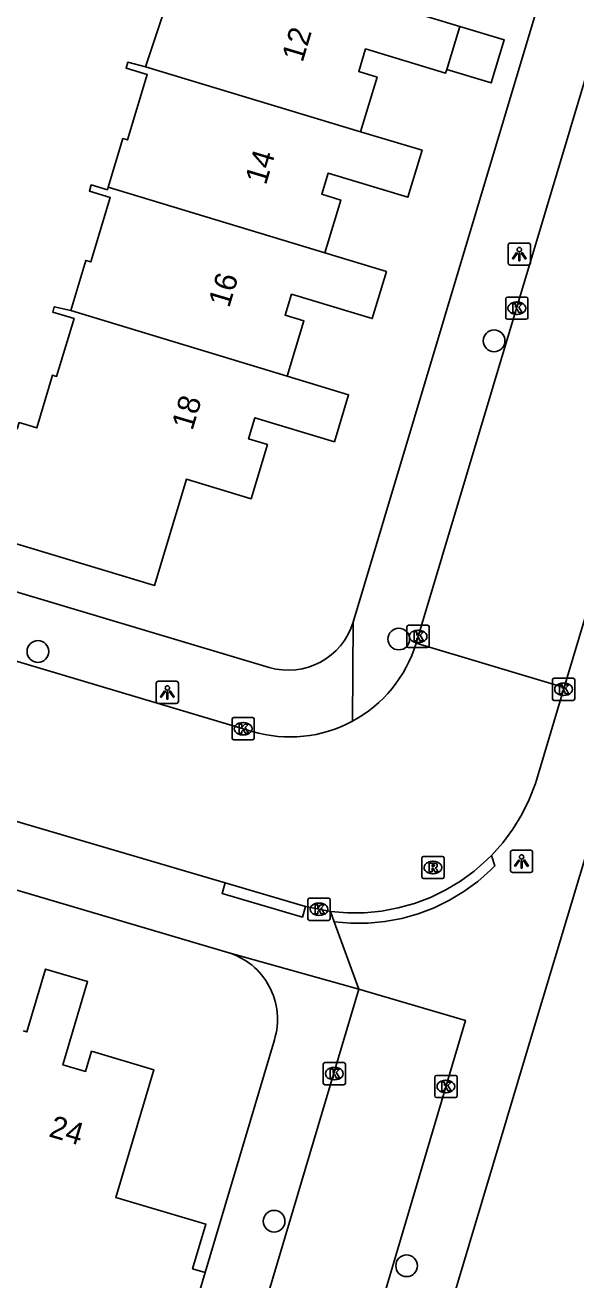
# Model space of a CAD drawing. Extents: x 162186 to 163152, y 385513 to 386513.
# Drawn here: x 162667.2 to 162692, y 386082.7 to 386139.3 of the extents above; entities that cross this region are included whole.
import ezdxf

# ---------------------------------------------------------------- set-up
doc = ezdxf.new("R2010")
doc.units = 0
for name, color, linetype in [('IMGEO_Boom', 7, 'Continuous'), ('IMGEO_Kolk', 7, 'Continuous'), ('IMGEO_Lichtpunt', 7, 'Continuous'), ('IMGEO_Pand', 7, 'Continuous'), ('IMGEO_Pand_nummerreeks', 7, 'Continuous'), ('IMGEO_Rijbaan_lokaal_open', 7, 'Continuous'), ('IMGEO_Rioolput', 7, 'Continuous'), ('IMGEO_Voetpad_open', 7, 'Continuous')]:
    doc.layers.add(name, color=color, linetype=linetype)

msp = doc.modelspace()

# ---------------------------------------------------------------- linework, layer by layer
at = {"layer": 'IMGEO_Boom'}
for centre in [(162688.354, 386125.044), (162684.062, 386111.611), (162667.801, 386111.048), (162678.444, 386085.382), (162684.416, 386083.376)]:
    msp.add_circle(centre, 0.489, dxfattribs=at)
at = {"layer": 'IMGEO_Kolk'}
for p, q in [((162688.957, 386127.013), (162689.809, 386127.013)), ((162688.882, 386126.087), (162688.882, 386126.939)), ((162689.37, 386126.793), (162689.395, 386126.793)), ((162689.883, 386126.939), (162689.883, 386126.087)), ((162689.809, 386126.013), (162688.957, 386126.013)), ((162689.393, 386126.233), (162689.368, 386126.233)), ((162684.431, 386111.302), (162684.431, 386112.154)), ((162684.506, 386112.228), (162685.358, 386112.228)), ((162684.919, 386112.008), (162684.944, 386112.008)), ((162685.432, 386112.154), (162685.432, 386111.302)), ((162685.358, 386111.228), (162684.506, 386111.228)), ((162684.942, 386111.448), (162684.917, 386111.448)), ((162690.987, 386108.92), (162690.987, 386109.772)), ((162691.062, 386109.846), (162691.914, 386109.846)), ((162691.475, 386109.626), (162691.5, 386109.626)), ((162691.988, 386109.772), (162691.988, 386108.92)), ((162691.498, 386109.066), (162691.473, 386109.066)), ((162691.914, 386108.846), (162691.062, 386108.846)), ((162676.549, 386107.144), (162676.549, 386107.996)), ((162676.624, 386108.07), (162677.476, 386108.07)), ((162677.037, 386107.85), (162677.062, 386107.85)), ((162677.55, 386107.996), (162677.55, 386107.144)), ((162677.06, 386107.29), (162677.035, 386107.29)), ((162677.476, 386107.07), (162676.624, 386107.07)), ((162679.967, 386099.011), (162679.967, 386099.863)), ((162680.042, 386099.937), (162680.894, 386099.937)), ((162680.968, 386099.863), (162680.968, 386099.011)), ((162680.455, 386099.717), (162680.48, 386099.717)), ((162680.894, 386098.937), (162680.042, 386098.937)), ((162680.478, 386099.157), (162680.453, 386099.157)), ((162680.73, 386092.532), (162681.582, 386092.532)), ((162680.655, 386091.606), (162680.655, 386092.458)), ((162681.143, 386092.312), (162681.168, 386092.312)), ((162681.656, 386092.458), (162681.656, 386091.606)), ((162685.759, 386091.954), (162686.611, 386091.954)), ((162681.582, 386091.532), (162680.73, 386091.532)), ((162681.166, 386091.752), (162681.141, 386091.752)), ((162685.684, 386091.028), (162685.684, 386091.88)), ((162686.172, 386091.734), (162686.197, 386091.734)), ((162686.685, 386091.88), (162686.685, 386091.028)), ((162686.611, 386090.954), (162685.759, 386090.954)), ((162686.195, 386091.174), (162686.17, 386091.174))]:
    msp.add_line(p, q, dxfattribs=at)
for points in [[(162688.957, 386127.013), (162689.809, 386127.013)], [(162688.882, 386126.087), (162688.882, 386126.939)], [(162689.203, 386126.713), (162689.326, 386126.713), (162689.326, 386126.562), (162689.456, 386126.713), (162689.62, 386126.713), (162689.474, 386126.562), (162689.627, 386126.313), (162689.475, 386126.313), (162689.39, 386126.477), (162689.326, 386126.41), (162689.326, 386126.313), (162689.203, 386126.313), (162689.203, 386126.713)], [(162689.883, 386126.939), (162689.883, 386126.087)], [(162689.809, 386126.013), (162688.957, 386126.013)], [(162684.431, 386111.302), (162684.431, 386112.154)], [(162684.506, 386112.228), (162685.358, 386112.228)], [(162684.752, 386111.928), (162684.875, 386111.928), (162684.875, 386111.777), (162685.005, 386111.928), (162685.169, 386111.928), (162685.023, 386111.777), (162685.176, 386111.528), (162685.024, 386111.528), (162684.939, 386111.692), (162684.875, 386111.625), (162684.875, 386111.528), (162684.752, 386111.528), (162684.752, 386111.928)], [(162685.432, 386112.154), (162685.432, 386111.302)], [(162685.358, 386111.228), (162684.506, 386111.228)], [(162690.987, 386108.92), (162690.987, 386109.772)], [(162691.062, 386109.846), (162691.914, 386109.846)], [(162691.308, 386109.546), (162691.431, 386109.546), (162691.431, 386109.395), (162691.561, 386109.546), (162691.725, 386109.546), (162691.579, 386109.395), (162691.732, 386109.146), (162691.58, 386109.146), (162691.495, 386109.31), (162691.431, 386109.243), (162691.431, 386109.146), (162691.308, 386109.146), (162691.308, 386109.546)], [(162691.988, 386109.772), (162691.988, 386108.92)], [(162691.914, 386108.846), (162691.062, 386108.846)], [(162676.549, 386107.144), (162676.549, 386107.996)], [(162676.624, 386108.07), (162677.476, 386108.07)], [(162676.87, 386107.77), (162676.993, 386107.77), (162676.993, 386107.619), (162677.123, 386107.77), (162677.287, 386107.77), (162677.141, 386107.619), (162677.294, 386107.37), (162677.142, 386107.37), (162677.057, 386107.534), (162676.993, 386107.467), (162676.993, 386107.37), (162676.87, 386107.37), (162676.87, 386107.77)], [(162677.55, 386107.996), (162677.55, 386107.144)], [(162677.476, 386107.07), (162676.624, 386107.07)], [(162679.967, 386099.011), (162679.967, 386099.863)], [(162680.042, 386099.937), (162680.894, 386099.937)], [(162680.968, 386099.863), (162680.968, 386099.011)], [(162680.288, 386099.637), (162680.411, 386099.637), (162680.411, 386099.486), (162680.541, 386099.637), (162680.705, 386099.637), (162680.559, 386099.486), (162680.712, 386099.237), (162680.56, 386099.237), (162680.475, 386099.401), (162680.411, 386099.334), (162680.411, 386099.237), (162680.288, 386099.237), (162680.288, 386099.637)], [(162680.894, 386098.937), (162680.042, 386098.937)], [(162680.73, 386092.532), (162681.582, 386092.532)], [(162680.655, 386091.606), (162680.655, 386092.458)], [(162680.976, 386092.232), (162681.099, 386092.232), (162681.099, 386092.081), (162681.229, 386092.232), (162681.393, 386092.232), (162681.247, 386092.081), (162681.4, 386091.832), (162681.248, 386091.832), (162681.163, 386091.996), (162681.099, 386091.929), (162681.099, 386091.832), (162680.976, 386091.832), (162680.976, 386092.232)], [(162681.656, 386092.458), (162681.656, 386091.606)], [(162685.759, 386091.954), (162686.611, 386091.954)], [(162681.582, 386091.532), (162680.73, 386091.532)], [(162685.684, 386091.028), (162685.684, 386091.88)], [(162686.005, 386091.654), (162686.128, 386091.654), (162686.128, 386091.503), (162686.258, 386091.654), (162686.422, 386091.654), (162686.276, 386091.503), (162686.429, 386091.254), (162686.277, 386091.254), (162686.192, 386091.418), (162686.128, 386091.351), (162686.128, 386091.254), (162686.005, 386091.254), (162686.005, 386091.654)], [(162686.685, 386091.88), (162686.685, 386091.028)], [(162686.611, 386090.954), (162685.759, 386090.954)]]:
    msp.add_lwpolyline(points, dxfattribs=at)
for centre, start, end in [((162688.959, 386126.937), 91.552, 178.448), ((162688.959, 386126.937), 91.552, 178.448), ((162689.807, 386126.937), 1.552, 88.448), ((162689.807, 386126.937), 1.552, 88.448), ((162688.959, 386126.089), 181.552, 268.448), ((162688.959, 386126.089), 181.552, 268.448), ((162689.807, 386126.089), 271.552, 358.448), ((162689.807, 386126.089), 271.552, 358.448), ((162684.508, 386112.152), 91.552, 178.448), ((162684.508, 386112.152), 91.552, 178.448), ((162685.356, 386112.152), 1.552, 88.448), ((162685.356, 386112.152), 1.552, 88.448), ((162684.508, 386111.304), 181.552, 268.448), ((162684.508, 386111.304), 181.552, 268.448), ((162685.356, 386111.304), 271.552, 358.448), ((162685.356, 386111.304), 271.552, 358.448), ((162691.064, 386109.77), 91.552, 178.448), ((162691.064, 386109.77), 91.552, 178.448), ((162691.912, 386109.77), 1.552, 88.448), ((162691.912, 386109.77), 1.552, 88.448), ((162691.064, 386108.922), 181.552, 268.448), ((162691.064, 386108.922), 181.552, 268.448), ((162691.912, 386108.922), 271.552, 358.448), ((162691.912, 386108.922), 271.552, 358.448), ((162676.626, 386107.994), 91.552, 178.448), ((162676.626, 386107.994), 91.552, 178.448), ((162677.474, 386107.994), 1.552, 88.448), ((162677.474, 386107.994), 1.552, 88.448), ((162676.626, 386107.146), 181.552, 268.448), ((162676.626, 386107.146), 181.552, 268.448), ((162677.474, 386107.146), 271.552, 358.448), ((162677.474, 386107.146), 271.552, 358.448), ((162680.044, 386099.861), 91.552, 178.448), ((162680.044, 386099.861), 91.552, 178.448), ((162680.892, 386099.861), 1.552, 88.448), ((162680.892, 386099.861), 1.552, 88.448), ((162680.044, 386099.013), 181.552, 268.448), ((162680.044, 386099.013), 181.552, 268.448), ((162680.892, 386099.013), 271.552, 358.448), ((162680.892, 386099.013), 271.552, 358.448), ((162680.732, 386092.456), 91.552, 178.448), ((162680.732, 386092.456), 91.552, 178.448), ((162681.58, 386092.456), 1.552, 88.448), ((162681.58, 386092.456), 1.552, 88.448), ((162685.761, 386091.878), 91.552, 178.448), ((162685.761, 386091.878), 91.552, 178.448), ((162686.609, 386091.878), 1.552, 88.448), ((162686.609, 386091.878), 1.552, 88.448), ((162680.732, 386091.608), 181.552, 268.448), ((162680.732, 386091.608), 181.552, 268.448), ((162681.58, 386091.608), 271.552, 358.448), ((162681.58, 386091.608), 271.552, 358.448), ((162685.761, 386091.03), 181.552, 268.448), ((162685.761, 386091.03), 181.552, 268.448), ((162686.609, 386091.03), 271.552, 358.448), ((162686.609, 386091.03), 271.552, 358.448)]:
    msp.add_arc(centre, 0.0765, start, end, dxfattribs=at)
for centre, major_axis, ratio, start_param, end_param in [((162689.369, 386126.513), (-0.387, 0.002), 0.722429, 4.712389, 7.853982), ((162689.394, 386126.513), (-0.39, 0.002), 0.717154, 1.570796, 4.712389), ((162684.918, 386111.728), (-0.387, 0.002), 0.722429, 4.712389, 7.853982), ((162684.943, 386111.728), (-0.39, 0.002), 0.717154, 1.570796, 4.712389), ((162691.474, 386109.346), (-0.387, 0.002), 0.722429, 4.712389, 7.853982), ((162691.499, 386109.346), (-0.39, 0.002), 0.717154, 1.570796, 4.712389), ((162677.036, 386107.57), (-0.387, 0.002), 0.722429, 4.712389, 7.853982), ((162677.061, 386107.57), (-0.39, 0.002), 0.717154, 1.570796, 4.712389), ((162680.454, 386099.437), (-0.387, 0.002), 0.722429, 4.712389, 7.853982), ((162680.479, 386099.437), (-0.39, 0.002), 0.717154, 1.570796, 4.712389), ((162681.142, 386092.032), (-0.387, 0.002), 0.722429, 4.712389, 7.853982), ((162681.167, 386092.032), (-0.39, 0.002), 0.717154, 1.570796, 4.712389), ((162686.171, 386091.454), (-0.387, 0.002), 0.722429, 4.712389, 7.853982), ((162686.196, 386091.454), (-0.39, 0.002), 0.717154, 1.570796, 4.712389)]:
    msp.add_ellipse(centre, major_axis=major_axis, ratio=ratio, start_param=start_param, end_param=end_param, dxfattribs=at)
at = {"layer": 'IMGEO_Lichtpunt'}
for p, q in [((162688.996, 386129.355), (162688.996, 386128.548)), ((162688.996, 386129.355), (162688.996, 386128.548)), ((162689.898, 386129.45), (162689.09, 386129.45)), ((162689.898, 386129.45), (162689.09, 386129.45)), ((162689.992, 386128.548), (162689.992, 386129.355)), ((162689.992, 386128.548), (162689.992, 386129.355)), ((162689.09, 386128.454), (162689.898, 386128.454)), ((162689.09, 386128.454), (162689.898, 386128.454)), ((162673.134, 386109.611), (162673.134, 386108.804)), ((162673.134, 386109.611), (162673.134, 386108.804)), ((162674.036, 386109.706), (162673.228, 386109.706)), ((162674.036, 386109.706), (162673.228, 386109.706)), ((162674.13, 386108.804), (162674.13, 386109.611)), ((162674.13, 386108.804), (162674.13, 386109.611)), ((162673.228, 386108.71), (162674.036, 386108.71)), ((162673.228, 386108.71), (162674.036, 386108.71)), ((162689.998, 386102.092), (162689.19, 386102.092)), ((162689.998, 386102.092), (162689.19, 386102.092)), ((162689.096, 386101.997), (162689.096, 386101.19)), ((162689.096, 386101.997), (162689.096, 386101.19)), ((162690.092, 386101.19), (162690.092, 386101.997)), ((162690.092, 386101.19), (162690.092, 386101.997)), ((162689.19, 386101.096), (162689.998, 386101.096)), ((162689.19, 386101.096), (162689.998, 386101.096))]:
    msp.add_line(p, q, dxfattribs=at)
for points in [[(162689.37, 386129.019), (162689.409, 386128.991), (162689.221, 386128.729), (162689.183, 386128.756), (162689.37, 386129.019)], [(162689.472, 386128.971), (162689.519, 386128.971), (162689.519, 386128.649), (162689.472, 386128.649), (162689.472, 386128.971)], [(162689.582, 386128.991), (162689.62, 386129.018), (162689.807, 386128.756), (162689.768, 386128.728), (162689.582, 386128.991)], [(162673.508, 386109.275), (162673.547, 386109.247), (162673.359, 386108.985), (162673.321, 386109.012), (162673.508, 386109.275)], [(162673.61, 386109.227), (162673.657, 386109.227), (162673.657, 386108.905), (162673.61, 386108.905), (162673.61, 386109.227)], [(162673.72, 386109.247), (162673.758, 386109.274), (162673.945, 386109.012), (162673.906, 386108.984), (162673.72, 386109.247)], [(162689.47, 386101.661), (162689.509, 386101.633), (162689.321, 386101.371), (162689.283, 386101.398), (162689.47, 386101.661)], [(162689.572, 386101.613), (162689.619, 386101.613), (162689.619, 386101.291), (162689.572, 386101.291), (162689.572, 386101.613)], [(162689.682, 386101.633), (162689.72, 386101.66), (162689.907, 386101.398), (162689.868, 386101.37), (162689.682, 386101.633)]]:
    msp.add_lwpolyline(points, dxfattribs=at)
for centre in [(162689.495, 386129.153), (162673.633, 386109.409), (162689.595, 386101.795)]:
    msp.add_circle(centre, 0.0994, dxfattribs=at)
for centre, start, end in [((162689.09, 386129.355), 90, 180), ((162689.09, 386129.355), 90, 180), ((162689.898, 386129.355), 0, 90), ((162689.898, 386129.355), 0, 90), ((162689.09, 386128.548), 180, 270), ((162689.09, 386128.548), 180, 270), ((162689.898, 386128.548), 270, 0), ((162689.898, 386128.548), 270, 360), ((162673.228, 386109.611), 90, 180), ((162673.228, 386109.611), 90, 180), ((162674.036, 386109.611), 0, 90), ((162674.036, 386109.611), 0, 90), ((162673.228, 386108.804), 180, 270), ((162673.228, 386108.804), 180, 270), ((162674.036, 386108.804), 270, 0), ((162674.036, 386108.804), 270, 360), ((162689.19, 386101.997), 90, 180), ((162689.19, 386101.997), 90, 180), ((162689.998, 386101.997), 0, 90), ((162689.998, 386101.997), 0, 90), ((162689.19, 386101.19), 180, 270), ((162689.19, 386101.19), 180, 270), ((162689.998, 386101.19), 270, 0), ((162689.998, 386101.19), 270, 360)]:
    msp.add_arc(centre, 0.0946, start, end, dxfattribs=at)
at = {"layer": 'IMGEO_Pand'}
for points in [[(162674.27, 386142.997), (162673.471, 386143.139), (162673.38, 386142.839), (162674.361, 386142.543), (162672.648, 386137.382)], [(162686.809, 386139.206), (162684.015, 386140.05)], [(162686.809, 386139.206), (162686.224, 386137.27)], [(162686.224, 386137.27), (162688.232, 386136.664), (162688.817, 386138.6), (162686.809, 386139.206)], [(162682.338, 386134.462), (162683.081, 386136.924), (162682.254, 386137.173), (162682.562, 386138.191), (162686.173, 386137.101), (162686.224, 386137.27)], [(162672.648, 386137.382), (162671.849, 386137.593), (162671.77, 386137.332), (162672.726, 386137.043), (162671.835, 386134.091), (162671.625, 386134.154), (162670.963, 386131.961)], [(162672.648, 386137.382), (162682.338, 386134.462)], [(162680.726, 386129.003), (162681.445, 386131.386), (162680.589, 386131.645), (162680.876, 386132.593), (162684.47, 386131.508), (162685.109, 386133.626), (162682.338, 386134.462)], [(162670.963, 386131.961), (162670.93, 386131.852), (162670.204, 386132.071), (162670.119, 386131.789), (162671.056, 386131.506), (162670.179, 386128.6), (162669.96, 386128.666), (162669.279, 386126.408)], [(162680.726, 386129.003), (162670.963, 386131.961)], [(162679.038, 386123.448), (162679.79, 386125.938), (162678.94, 386126.194), (162679.227, 386127.145), (162682.863, 386126.048), (162683.502, 386128.165), (162680.726, 386129.003)], [(162669.279, 386126.408), (162668.538, 386126.577), (162668.466, 386126.339), (162669.429, 386126.048), (162668.642, 386123.442), (162668.46, 386123.497), (162667.744, 386121.124), (162666.948, 386121.364), (162666.86, 386121.072), (162664.918, 386121.658), (162663.483, 386116.902), (162673.046, 386114.016), (162674.491, 386118.805), (162677.404, 386117.926), (162678.142, 386120.371), (162677.291, 386120.627), (162677.578, 386121.579), (162681.158, 386120.499), (162681.797, 386122.615), (162679.038, 386123.448)], [(162669.279, 386126.408), (162679.038, 386123.448)], [(162667.13, 386093.961), (162667.304, 386093.909), (162668.146, 386096.744), (162670.036, 386096.182), (162668.923, 386092.435), (162669.949, 386092.13), (162670.22, 386093.04), (162673.016, 386092.209), (162671.307, 386086.458), (162675.364, 386085.253), (162674.766, 386083.24), (162675.341, 386083.069)], [(162675.341, 386083.069), (162673.803, 386077.892)]]:
    msp.add_lwpolyline(points, dxfattribs=at)
at = {"layer": 'IMGEO_Rijbaan_lokaal_open'}
for points in [[(162684.842, 386111.426), (162710.296, 386196.346)], [(162677.459, 386107.446), (162651.748, 386115.1), (162602.19, 386130.13), (162581.53, 386136.322), (162581.327, 386136.385)], [(162697.472, 386129.304), (162691.517, 386109.426)], [(162676.239, 386100.629), (162651.463, 386107.909), (162608.761, 386120.695)], [(162691.517, 386109.426), (162684.842, 386111.426)], [(162691.517, 386109.426), (162690.312, 386105.402), (162690.217, 386105.102), (162689.939, 386104.388), (162689.6, 386103.703), (162689.2, 386103.05), (162688.743, 386102.436), (162688.234, 386101.865)], [(162680.986, 386099.343), (162681.75, 386099.278), (162682.517, 386099.282), (162683.28, 386099.355), (162684.034, 386099.495), (162684.772, 386099.702), (162685.489, 386099.974), (162686.179, 386100.309), (162686.836, 386100.705), (162687.455, 386101.157), (162688.031, 386101.663), (162688.234, 386101.865)], [(162676.239, 386100.629), (162679.856, 386099.566)], [(162680.986, 386099.343), (162679.856, 386099.566)], [(162662.333, 386028.923), (162682.265, 386095.831)], [(162682.265, 386095.831), (162687.061, 386094.431), (162672.384, 386044.868)]]:
    msp.add_lwpolyline(points, dxfattribs=at)
for centre, radius, start, end in [((162679.16, 386113.134), 5.934, 298.3036, 343.2686), ((162679.155, 386113.139), 5.941, 253.4153, 298.3225)]:
    msp.add_arc(centre, radius, start, end, dxfattribs=at)
at = {"layer": 'IMGEO_Rioolput'}
for p, q in [((162685.1, 386100.893), (162685.1, 386101.745)), ((162685.175, 386101.819), (162686.027, 386101.819)), ((162685.588, 386101.599), (162685.613, 386101.599)), ((162686.101, 386101.745), (162686.101, 386100.893)), ((162685.611, 386101.039), (162685.586, 386101.039)), ((162686.027, 386100.819), (162685.175, 386100.819))]:
    msp.add_line(p, q, dxfattribs=at)
for points in [[(162685.1, 386100.893), (162685.1, 386101.745)], [(162685.175, 386101.819), (162686.027, 386101.819)], [(162685.689, 386101.517), (162685.437, 386101.519), (162685.437, 386101.119)], [(162686.101, 386101.745), (162686.101, 386100.893)], [(162685.437, 386101.119), (162685.561, 386101.119), (162685.561, 386101.281), (162685.572, 386101.281)], [(162685.615, 386101.438), (162685.561, 386101.438), (162685.561, 386101.357)], [(162685.561, 386101.357), (162685.613, 386101.357)], [(162685.619, 386101.252), (162685.69, 386101.119), (162685.83, 386101.119), (162685.765, 386101.245)], [(162686.027, 386100.819), (162685.175, 386100.819)]]:
    msp.add_lwpolyline(points, dxfattribs=at)
for centre, radius, start, end in [((162685.177, 386101.743), 0.0765, 91.552, 178.448), ((162685.177, 386101.743), 0.0765, 91.552, 178.448), ((162685.688, 386101.407), 0.109, 350.3612, 89.416), ((162686.025, 386101.743), 0.0765, 1.552, 88.448), ((162686.025, 386101.743), 0.0765, 1.552, 88.448), ((162685.571, 386101.228), 0.0533, 26.0293, 88.6989), ((162685.597, 386101.546), 0.19, 274.7715, 282.9687), ((162685.621, 386101.342), 0.0964, 77.0061, 93.1865), ((162685.635, 386101.399), 0.0378, 276.6634, 79.6772), ((162685.686, 386101.407), 0.112, 277.5842, 350.9817), ((162685.67, 386101.192), 0.108, 29.5134, 73.7905), ((162685.177, 386100.895), 0.0765, 181.552, 268.448), ((162685.177, 386100.895), 0.0765, 181.552, 268.448), ((162686.025, 386100.895), 0.0765, 271.552, 358.448), ((162686.025, 386100.895), 0.0765, 271.552, 358.448)]:
    msp.add_arc(centre, radius, start, end, dxfattribs=at)
for centre, major_axis, ratio, start_param, end_param in [((162685.587, 386101.319), (-0.387, 0.002), 0.722429, 4.712389, 7.853982), ((162685.612, 386101.319), (-0.39, 0.002), 0.717154, 1.570796, 4.712389)]:
    msp.add_ellipse(centre, major_axis=major_axis, ratio=ratio, start_param=start_param, end_param=end_param, dxfattribs=at)
at = {"layer": 'IMGEO_Voetpad_open'}
for points in [[(162697.274, 386163.359), (162697.211, 386163.095), (162682.002, 386112.374)], [(162676.361, 386097.494), (162605.955, 386118.287)], [(162678.215, 386110.332), (162659.122, 386116.038), (162658.987, 386116.082)], [(162682.002, 386112.374), (162681.973, 386107.91)], [(162675.165, 386044.035), (162690.004, 386093.566), (162693.881, 386106.506)], [(162688.234, 386101.865), (162688.392, 386101.391), (162688.196, 386101.196), (162687.62, 386100.689), (162687, 386100.236), (162686.342, 386099.84), (162685.652, 386099.504), (162684.934, 386099.231), (162684.195, 386099.023), (162683.44, 386098.882), (162682.676, 386098.809), (162681.908, 386098.805), (162681.143, 386098.869)], [(162679.856, 386099.566), (162679.716, 386099.087), (162676.099, 386100.15), (162676.239, 386100.629)], [(162681.143, 386098.869), (162680.986, 386099.343)], [(162682.265, 386095.831), (162681.143, 386098.869)], [(162676.361, 386097.494), (162682.265, 386095.831)], [(162675.341, 386083.069), (162678.454, 386093.552)]]:
    msp.add_lwpolyline(points, dxfattribs=at)
for centre, radius, start, end in [((162679.087, 386113.248), 3.043, 253.3556, 343.3127), ((162675.444, 386094.481), 3.15, 342.854, 73.078)]:
    msp.add_arc(centre, radius, start, end, dxfattribs=at)

# ---------------------------------------------------------------- texts
at = {"layer": 'IMGEO_Pand_nummerreeks'}
for s, rotation, p in [('12', 73.3443, (162679.725, 386137.553)), ('14', 73.342, (162678.071, 386132.026)), ('16', 73.342, (162676.416, 386126.495)), ('18', 73.342, (162674.762, 386120.968)), ('24', 343.4402, (162668.246, 386089.214))]:
    msp.add_text(s, height=1, rotation=rotation, dxfattribs=at).set_placement(p)

doc.saveas('drawing.dxf')
